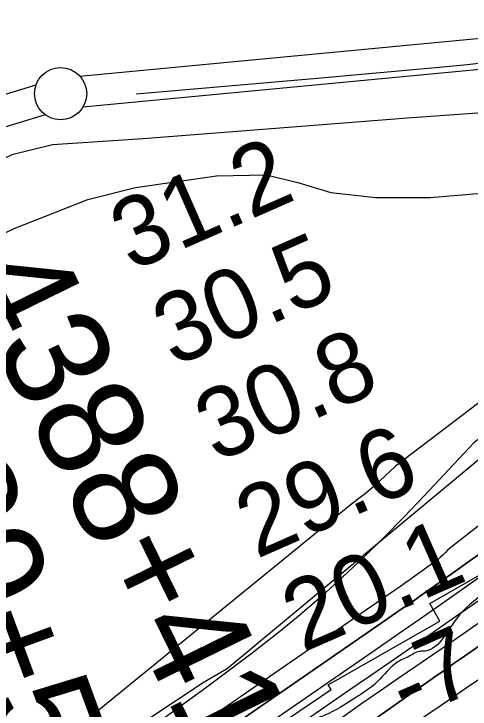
# Model space of a CAD drawing. Extents: x 3297753 to 3335611, y 652252 to 677623.
# Drawn here: x 3315180 to 3315617, y 659818 to 660484 of the extents above; entities that cross this region are included whole.
import ezdxf

# ---------------------------------------------------------------- set-up
doc = ezdxf.new("R2010")
doc.units = 0
for name, color, linetype in [('V-FLOD-BASE', 7, 'Continuous'), ('V-LEVE-TOET', 7, 'Continuous'), ('V-RIVR-EDGE', 7, 'Continuous'), ('V-RIVR-RANG', 7, 'Continuous'), ('V-RRAP-RVMT', 7, 'Continuous'), ('V-SITE-VEGE', 7, 'Continuous'), ('V-SURV-IDEN', 7, 'Continuous'), ('V-SURV-LINE', 7, 'Continuous'), ('V-TOPO-DPTH', 7, 'Continuous'), ('V-TOPO-MAJR', 7, 'Continuous'), ('V-TOPO-MINR', 7, 'Continuous'), ('V-TOPO-WATR', 7, 'Continuous')]:
    doc.layers.add(name, color=color, linetype=linetype)

msp = doc.modelspace()

# ---------------------------------------------------------------- linework, layer by layer
at = {"layer": 'V-FLOD-BASE'}
for points in [[(3316674.14, 661265.47), (3316565.33, 661220.83), (3316432.43, 661161.1), (3316376.97, 661134.6), (3316345.04, 661114.31), (3316312.05, 661088.79), (3316268.03, 661045.02), (3316154.84, 660928.8), (3316046.88, 660815.7), (3315945.75, 660714.08), (3315862.43, 660628.08), (3315782.25, 660545.22), (3315706.79, 660469.65), (3315688.46, 660455.59), (3315669.62, 660444.67), (3315641.38, 660437.96), (3315613.68, 660434.9), (3315590.41, 660432.45)], [(3315590.41, 660432.45), (3315466.73, 660421.39), (3315296.93, 660406.74)]]:
    msp.add_lwpolyline(points, dxfattribs=at)
at = {"layer": 'V-LEVE-TOET'}
msp.add_lwpolyline([(3315628.07, 660388.92), (3315556.65, 660383.64), (3315459.11, 660376.02), (3315303.42, 660363.9), (3315216.76, 660358.17), (3315177.93, 660348.79), (3315125.89, 660323.76), (3315061.19, 660277.22), (3314977.09, 660212.51), (3314914.91, 660160.18), (3314894.54, 660135.32), (3314882.42, 660109.14), (3314809, 660079.85)], dxfattribs=at)
at = {"layer": 'V-RIVR-EDGE'}
msp.add_spline([(3319472.94, 662096.79), (3319451.36, 662084.83), (3319431.44, 662073.27), (3319412.76, 662065.44), (3319386.64, 662059.7), (3319355.13, 662056.05), (3319321.53, 662047.43), (3319286.69, 662035.91), (3319261.79, 662024.37), (3319253.91, 662022.31), (3319243.96, 662022.34), (3319236.91, 662020.28), (3319220.3, 662007.06), (3319214.06, 661999.2), (3319197.88, 661992.61), (3319174.65, 661985.21), (3319135.25, 661974.53), (3319095.84, 661962.6), (3319061.83, 661950.67), (3319035.69, 661940.78), (3319017.02, 661932.54), (3319004.15, 661925.11), (3318977.6, 661914.4), (3318949.4, 661908.67), (3318929.07, 661903.33), (3318893.41, 661894.3), (3318836.17, 661878.69), (3318802.16, 661869.66), (3318784.32, 661864.31), (3318761.1, 661859.4), (3318735.37, 661848.27), (3318707.16, 661836.32), (3318683.94, 661831.82), (3318667.77, 661829.78), (3318647.86, 661824.86), (3318612.18, 661812.51), (3318583.56, 661801.39), (3318550.78, 661789.45), (3318517.19, 661780.83), (3318486.91, 661770.55), (3318459.1, 661757.77), (3318437.11, 661748.7), (3318401.09, 661732.56), (3318376.27, 661719.66), (3318350.33, 661712.4), (3318322.69, 661702.89), (3318295.62, 661690.56), (3318275.88, 661686.66), (3318257.84, 661681.07), (3318243.73, 661673.22), (3318214.4, 661661.46), (3318180.55, 661645.76), (3318148.4, 661630.07), (3318131.47, 661619.4), (3318111.14, 661604.8), (3318079.51, 661575.01), (3318056.38, 661560.42), (3318032.66, 661542.45), (3318016.3, 661532.35), (3317961.53, 661489.66), (3317862.74, 661415.52), (3317830, 661391.93), (3317829.43, 661388.56), (3317827.16, 661382.93), (3317810.8, 661375.64), (3317785.97, 661359.92), (3317761.13, 661342.52), (3317743.62, 661322.84), (3317726.09, 661300.91), (3317708.57, 661278.97), (3317696.72, 661270.55), (3317673.58, 661255.39), (3317601.32, 661201.48), (3317560.67, 661171.71), (3317529.07, 661153.2), (3317513.82, 661140.27), (3317483.9, 661117.24), (3317464.15, 661105.46), (3317423.52, 661083.02), (3317409.43, 661079.11), (3317401.54, 661079.13), (3317375.02, 661065.67), (3317364.3, 661058.94), (3317348.5, 661051.09), (3317330.46, 661046.62), (3317307.32, 661033.16), (3317289.27, 661024.75), (3317263.88, 661012.42), (3317240.77, 661008.53), (3317230.05, 661004.05), (3317228.35, 661000.11), (3317221.59, 660998.43), (3317196.21, 660991.17), (3317170.27, 660981.66), (3317149.41, 660978.33), (3317103.16, 660960.97), (3317073.27, 660949.78), (3317034.34, 660929.59), (3316995.97, 660909.96), (3316948.02, 660886.98), (3316914.74, 660873.53), (3316885.97, 660860.65), (3316880.89, 660856.15), (3316871.29, 660848.28), (3316865.65, 660846.61), (3316855.51, 660846.63), (3316850.44, 660846.65), (3316844.22, 660840.46), (3316839.71, 660839.91), (3316835.77, 660840.48), (3316830.69, 660836.55), (3316818.84, 660828.69), (3316813.76, 660828.14), (3316808.13, 660827.03), (3316803.62, 660827.04), (3316796.84, 660818.6), (3316784.98, 660809.62), (3316774.82, 660802.88), (3316771.42, 660796.13), (3316765.18, 660779.24), (3316755.55, 660759.54), (3316745.94, 660744.35), (3316732.38, 660728.61), (3316712.63, 660717.95), (3316683.85, 660703.37), (3316676.52, 660701.13), (3316664.67, 660695.53), (3316651.68, 660680.34), (3316633.05, 660666.87), (3316616.12, 660656.2), (3316590.15, 660637.11), (3316544.42, 660603.41), (3316510, 660580.96), (3316472.73, 660551.75), (3316428.71, 660523.12), (3316390.32, 660495.6), (3316363.8, 660477.64), (3316349.69, 660469.78), (3316341.23, 660464.73), (3316335.03, 660464.75), (3316325.45, 660464.77), (3316313.61, 660461.42), (3316289.93, 660456.97), (3316257.21, 660443.53), (3316237.47, 660436.25), (3316207.01, 660423.93), (3316177.1, 660405.41), (3316154.53, 660393.07), (3316131.95, 660375.09), (3316110.5, 660362.19), (3316095.27, 660353.21), (3316080.02, 660338.03), (3316051.22, 660312.74), (3316013.92, 660270.58), (3315988.5, 660245.84), (3315960.26, 660217.18), (3315939.93, 660200.89), (3315925.81, 660185.14), (3315911.13, 660173.91), (3315895.32, 660159.86), (3315882.88, 660145.8), (3315867.63, 660130.06), (3315849.01, 660119.97), (3315837.71, 660109.29), (3315808.9, 660080.06), (3315786.88, 660062.08), (3315758.09, 660038.49), (3315733.81, 660018.83), (3315725.32, 660002.51), (3315692.01, 659976.67), (3315659.82, 659949.14), (3315603.36, 659904.2), (3315571.16, 659873.28), (3315569.47, 659873.29), (3315558.76, 659868.81), (3315547.47, 659863.2), (3315527.7, 659844.09), (3315506.25, 659828.37), (3315477.47, 659812.1), (3315461.12, 659805.94), (3315440.8, 659793.59), (3315429.5, 659781.79), (3315402.4, 659758.19), (3315361.76, 659731.8), (3315304.2, 659696.45), (3315255.66, 659666.7), (3315169.91, 659624.65), (3315140.01, 659611.76), (3315123.65, 659603.35), (3315098.82, 659588.76), (3315044.63, 659551.14), (3314989.87, 659507.33), (3314954.29, 659474.73), (3314933.97, 659462.39), (3314926.06, 659452.83), (3314915.88, 659440.45), (3314897.81, 659423.59), (3314866.75, 659396.06), (3314844.73, 659376.39), (3314848.66, 659370.75), (3314824.95, 659355.03), (3314801.82, 659342.69), (3314762.32, 659320.81), (3314730.16, 659303.42), (3314710.97, 659290.51), (3314664.68, 659256.25), (3314628.56, 659235.49), (3314603.16, 659218.09), (3314584.55, 659209.68), (3314564.82, 659208.04), (3314555.8, 659204.68), (3314546.76, 659196.25), (3314528.11, 659174.88), (3314492.47, 659118.62), (3314473.82, 659095), (3314450.67, 659074.77), (3314428.65, 659060.18), (3314423, 659054.56), (3314416.22, 659044.43), (3314398.14, 659027.57), (3314375.56, 659007.9), (3314366.53, 659005.11), (3314353.57, 659002.32), (3314347.36, 658997.27), (3314346.77, 658988.82), (3314351.26, 658983.17), (3314350.68, 658974.16), (3314342.76, 658961.78), (3314329.22, 658955.05), (3314311.71, 658940.44), (3314310, 658930.31), (3314294.2, 658921.89), (3314283.48, 658914.59), (3314276.12, 658903.91), (3314272.72, 658896.02), (3314237.73, 658871.32), (3314206.69, 658853.36), (3314198.23, 658851.13), (3314192.03, 658850.58), (3314180.19, 658846.1), (3314172.28, 658836.54), (3314164.36, 658823.6), (3314142.35, 658810.13), (3314120.89, 658792.72), (3314097.19, 658778.69), (3314086.46, 658769.14), (3314082.5, 658762.95), (3314080.22, 658754.5), (3314072.33, 658750.01), (3314036.79, 658734.32), (3314006.33, 658722), (3313997.3, 658716.39), (3313939.72, 658673.71), (3313888.34, 658634.95), (3313863.5, 658615.29), (3313820.61, 658586.66), (3313772.64, 658558.04), (3313732, 658532.78), (3313718.46, 658524.37), (3313711.13, 658521.57), (3313702.68, 658521.59), (3313693.09, 658518.79), (3313674.48, 658511.51), (3313646.82, 658494.68), (3313626.5, 658478.95), (3313619.73, 658475.02), (3313610.12, 658464.34), (3313605.01, 658449.14), (3313597.11, 658444.65), (3313577.92, 658428.92), (3313554.76, 658407.56), (3313537.8, 658387.32), (3313525.35, 658364.25), (3313506.11, 658331.61), (3313489.72, 658309.68)], degree=3, dxfattribs=at)
at = {"layer": 'V-RRAP-RVMT'}
for p, q in [((3315578.1, 659918.9), (3315669.14, 659971.57)), ((3315587.73, 659902.18), (3315578.1, 659918.9)), ((3315480.65, 659841.25), (3315587.73, 659902.18)), ((3315483.41, 659836.67), (3315480.65, 659841.25)), ((3315381.8, 659768.24), (3315483.41, 659836.67))]:
    msp.add_line(p, q, dxfattribs=at)
at = {"layer": 'V-SITE-VEGE'}
for points in [[(3315131.65, 660254.91), (3315180.12, 660278.01), (3315250.47, 660305.81), (3315296.35, 660317.46), (3315373.79, 660328.6), (3315421.46, 660329.66), (3315451.77, 660322.14), (3315483.25, 660312.44), (3315526.31, 660307.87), (3315578.46, 660307.67), (3315627.42, 660311.98), (3315629.67, 660311.98), (3315631.92, 660312.54), (3315633.6, 660311.41), (3315636.41, 660311.96), (3315639.78, 660311.39)], [(3315624.47, 660056.3), (3315383.96, 659856.34), (3315361.96, 659843.57), (3315309.08, 659808.59), (3315265.44, 659783.43), (3315212.53, 659761.66), (3315157.35, 659742.02)]]:
    msp.add_lwpolyline(points, dxfattribs=at)
at = {"layer": 'V-SURV-LINE'}
for points in [[(3315242.93, 660424.05), (3315660.39, 660463.69)], [(3315663.23, 660433.82), (3315245.77, 660394.19)], [(3315146.21, 660399.02), (3315200.96, 660415.74)], [(3315209.74, 660387.05), (3315154.99, 660370.33)]]:
    msp.add_lwpolyline(points, dxfattribs=at)
msp.add_circle((3315224.47, 660407.23), 25, dxfattribs=at)
at = {"layer": 'V-TOPO-DPTH'}
for points in [[(3316812.25, 660763.7), (3316305.76, 660404.28), (3316305.19, 660403.85), (3316301.19, 660400.87), (3316299.27, 660399.51), (3316296.19, 660397.34), (3316293.11, 660395.15), (3315855.8, 660039.96), (3315832.59, 660022.84), (3315611.09, 659868.46), (3315607.21, 659865.79), (3315605.25, 659864.47), (3315601.33, 659861.85), (3315597.45, 659859.17), (3315595.52, 659857.81), (3315592.25, 659855.46), (3315590.67, 659854.34), (3315587.51, 659852.09), (3315585.92, 659850.97), (3315318.35, 659662.28), (3315253.45, 659616.8), (3315188.38, 659571.58), (3315123.05, 659526.74)], [(3315123.05, 659526.74), (3315188.38, 659571.58), (3315253.45, 659616.8), (3315318.35, 659662.28), (3315585.92, 659850.97), (3315587.51, 659852.09), (3315590.67, 659854.34), (3315592.25, 659855.46), (3315595.52, 659857.81), (3315597.45, 659859.17), (3315601.33, 659861.85), (3315605.25, 659864.47), (3315607.21, 659865.79), (3315611.09, 659868.46), (3315832.59, 660022.84), (3315855.8, 660039.96), (3316293.11, 660395.15), (3316296.19, 660397.34), (3316299.27, 660399.51), (3316301.19, 660400.87), (3316305.19, 660403.85), (3316305.76, 660404.28), (3316812.25, 660763.7)], [(3316393.47, 660519.95), (3316326.32, 660473.83), (3316303.67, 660458.43), (3316280.93, 660443.17), (3316258.05, 660428.11), (3316235.08, 660413.19), (3315760.98, 660019.04), (3315746.23, 660007.34), (3315731.07, 659996.13), (3315630.41, 659925.53), (3315602.71, 659906.17), (3315574.97, 659886.88), (3315547.16, 659867.69), (3315519.3, 659848.56), (3315501.59, 659836.44), (3315464.96, 659811.15), (3315428.48, 659785.64), (3315392.23, 659759.81), (3315356.12, 659733.77), (3315323.44, 659709.99), (3315275.09, 659674.94), (3315226.66, 659640.01), (3315178.1, 659605.26)], [(3316393.47, 660519.95), (3316326.32, 660473.83), (3316303.67, 660458.43), (3316280.93, 660443.17), (3316258.05, 660428.11), (3316235.08, 660413.19), (3315760.98, 660019.04), (3315746.23, 660007.34), (3315731.07, 659996.13), (3315630.41, 659925.53), (3315602.71, 659906.17), (3315574.97, 659886.88), (3315547.16, 659867.69), (3315519.3, 659848.56), (3315501.59, 659836.44), (3315464.96, 659811.15), (3315428.48, 659785.64), (3315392.23, 659759.81), (3315356.12, 659733.77), (3315323.44, 659709.99), (3315275.09, 659674.94), (3315226.66, 659640.01), (3315178.1, 659605.26)], [(3315105.06, 659601.47), (3315180.53, 659655.43), (3315256.21, 659709.1), (3315332.2, 659762.32), (3315408.4, 659815.26), (3315535.71, 659903.15), (3315548.39, 659911.94), (3315561.05, 659920.76), (3315573.67, 659929.63), (3315586.27, 659938.54), (3315630.78, 659970.1), (3315637.62, 659975.2), (3315644.28, 659980.51), (3315650.68, 659986.13), (3315656.9, 659991.95), (3316254.04, 660467.92), (3316261.92, 660472.69), (3316269.76, 660477.52), (3316277.54, 660482.45), (3316285.29, 660487.42)]]:
    msp.add_lwpolyline(points, dxfattribs=at)
at = {"layer": 'V-TOPO-MAJR'}
msp.add_lwpolyline([(3316221.03, 660564.65), (3315545.19, 660050.47), (3315529.9, 660036.32), (3315523.02, 660030.17), (3315516, 660024.19), (3315508.77, 660018.47), (3315501.4, 660012.92), (3315022.88, 659623.25), (3314997.3, 659603.95), (3314971.52, 659584.94), (3314945.43, 659566.36), (3314919.13, 659548.06), (3314892.72, 659529.92), (3314866.35, 659511.71), (3314840.07, 659493.39), (3314813.83, 659474.99), (3314449.83, 659218.59), (3314385.65, 659170.92), (3314323.18, 659121.21)], dxfattribs=at)
at = {"layer": 'V-TOPO-MINR'}
for points in [[(3316812.25, 660763.7), (3316305.76, 660404.28), (3316305.19, 660403.85), (3316301.19, 660400.87), (3316299.27, 660399.51), (3316296.19, 660397.34), (3316293.11, 660395.15), (3315855.8, 660039.96), (3315832.59, 660022.84), (3315611.09, 659868.46), (3315607.21, 659865.79), (3315605.25, 659864.47), (3315601.33, 659861.85), (3315597.45, 659859.17), (3315595.52, 659857.81), (3315592.25, 659855.46), (3315590.67, 659854.34), (3315587.51, 659852.09), (3315585.92, 659850.97), (3315318.35, 659662.28), (3315253.45, 659616.8), (3315188.38, 659571.58), (3315123.05, 659526.74)], [(3316434.34, 660526.88), (3316321.67, 660446.08), (3316304.79, 660434.07), (3316287.85, 660422.14), (3315800.56, 660023.5), (3315781.27, 660009.31), (3315615.61, 659893.92), (3315598.69, 659882.17), (3315581.74, 659870.47), (3315564.76, 659858.82), (3315547.74, 659847.21), (3315530.77, 659835.55), (3315513.86, 659823.78), (3315497.08, 659811.85), (3315480.37, 659799.81), (3315467.09, 659790.15), (3315443.76, 659773.24), (3315420.4, 659756.39), (3315396.97, 659739.62), (3315373.5, 659722.92), (3315203.83, 659602.62), (3315156.79, 659569.42)], [(3316205.9, 660519.32), (3315620.59, 660073.28), (3315615.83, 660067.99), (3315572.39, 660021.67), (3315553.47, 660001.91), (3315534.29, 659982.42), (3315514.7, 659963.34), (3315494.84, 659944.52), (3315474.52, 659926.21), (3315453.87, 659908.3), (3315432.72, 659890.99), (3315411.22, 659874.08), (3315409.07, 659872.44), (3315386.17, 659855.12), (3315363.16, 659837.94), (3315339.99, 659820.98), (3315316.72, 659804.17), (3315165.54, 659696.04)], [(3316352.53, 660512.41), (3316304.96, 660480.74), (3316290.04, 660470.92), (3316275.06, 660461.2), (3316259.98, 660451.64), (3316244.84, 660442.18), (3315722.93, 660018.19), (3315712.93, 660008.8), (3315702.64, 659999.77), (3315691.92, 659991.25), (3315680.92, 659983.07), (3315608.54, 659932.01), (3315588.33, 659917.8), (3315568.08, 659903.64), (3315547.79, 659889.55), (3315527.46, 659875.51), (3315455.36, 659825.9), (3315399.11, 659786.87), (3315343.07, 659747.54), (3315287.35, 659707.77), (3315231.84, 659667.7), (3315072.49, 659551.73)], [(3316285.29, 660487.42), (3316277.54, 660482.45), (3316269.76, 660477.52), (3316261.92, 660472.69), (3316254.04, 660467.92), (3315656.9, 659991.95), (3315650.68, 659986.13), (3315644.28, 659980.51), (3315637.62, 659975.2), (3315630.78, 659970.1), (3315586.27, 659938.54), (3315573.67, 659929.63), (3315561.05, 659920.76), (3315548.39, 659911.94), (3315535.71, 659903.15), (3315408.4, 659815.26), (3315332.2, 659762.32), (3315256.21, 659709.1), (3315180.53, 659655.43), (3315105.06, 659601.47)], [(3316262.86, 660491.57), (3315595.35, 659970.44), (3315593.1, 659968.04), (3315590.79, 659965.69), (3315588.38, 659963.43), (3315585.91, 659961.26), (3315583.33, 659959.21), (3315580.7, 659957.23), (3315563.66, 659945.1), (3315558.78, 659941.64), (3315553.89, 659938.19), (3315548.98, 659934.76), (3315544.06, 659931.35), (3315304.72, 659766.2), (3315234.66, 659717.75), (3315164.67, 659669.2)], [(3316290.16, 660369.45), (3315758.1, 659938.87), (3315743.78, 659928.56), (3315729.34, 659918.4), (3315714.84, 659908.35), (3315700.29, 659898.36), (3315685.75, 659888.35), (3315671.23, 659878.32), (3315656.72, 659868.27), (3315625.44, 659846.57), (3315612.94, 659837.93), (3315600.42, 659829.31), (3315587.87, 659820.73), (3315575.3, 659812.18), (3315438.93, 659719.69), (3315358.06, 659665.07), (3315277.05, 659610.66), (3315195.84, 659556.55), (3315114.49, 659502.64)]]:
    msp.add_lwpolyline(points, dxfattribs=at)
at = {"layer": 'V-TOPO-WATR'}
msp.add_lwpolyline([(3316393.47, 660519.95), (3316326.32, 660473.83), (3316303.67, 660458.43), (3316280.93, 660443.17), (3316258.05, 660428.11), (3316235.08, 660413.19), (3315760.98, 660019.04), (3315746.23, 660007.34), (3315731.07, 659996.13), (3315630.41, 659925.53), (3315602.71, 659906.17), (3315574.97, 659886.88), (3315547.16, 659867.69), (3315519.3, 659848.56), (3315501.59, 659836.44), (3315464.96, 659811.15), (3315428.48, 659785.64), (3315392.23, 659759.81), (3315356.12, 659733.77), (3315323.44, 659709.99), (3315275.09, 659674.94), (3315226.66, 659640.01), (3315178.1, 659605.26)], dxfattribs=at)

# ---------------------------------------------------------------- texts
at = {"layer": 'V-RIVR-RANG'}
for s, rotation, p in [('31.2', 23.73833, (3315292.25, 660236.52)), ('30.5', 23.73833, (3315332.73, 660145.08)), ('30.8', 23.73833, (3315373.21, 660053.65)), ('29.6', 23.73833, (3315412.01, 659961.46)), ('20.1', 23.73833, (3315456.36, 659871.72)), ('-7', 24.02292, (3315556.01, 659806.03))]:
    msp.add_text(s, height=67, rotation=rotation, dxfattribs=at).set_placement(p)
at = {"layer": 'V-SURV-IDEN'}
for s, rotation, p in [('4388+41.8', 296.10936, (3315127.26, 660233.42)), ('4389+51.2', 290.22211, (3315021.53, 660179.13))]:
    msp.add_text(s, height=100, rotation=rotation, dxfattribs=at).set_placement(p)

doc.saveas('drawing.dxf')
